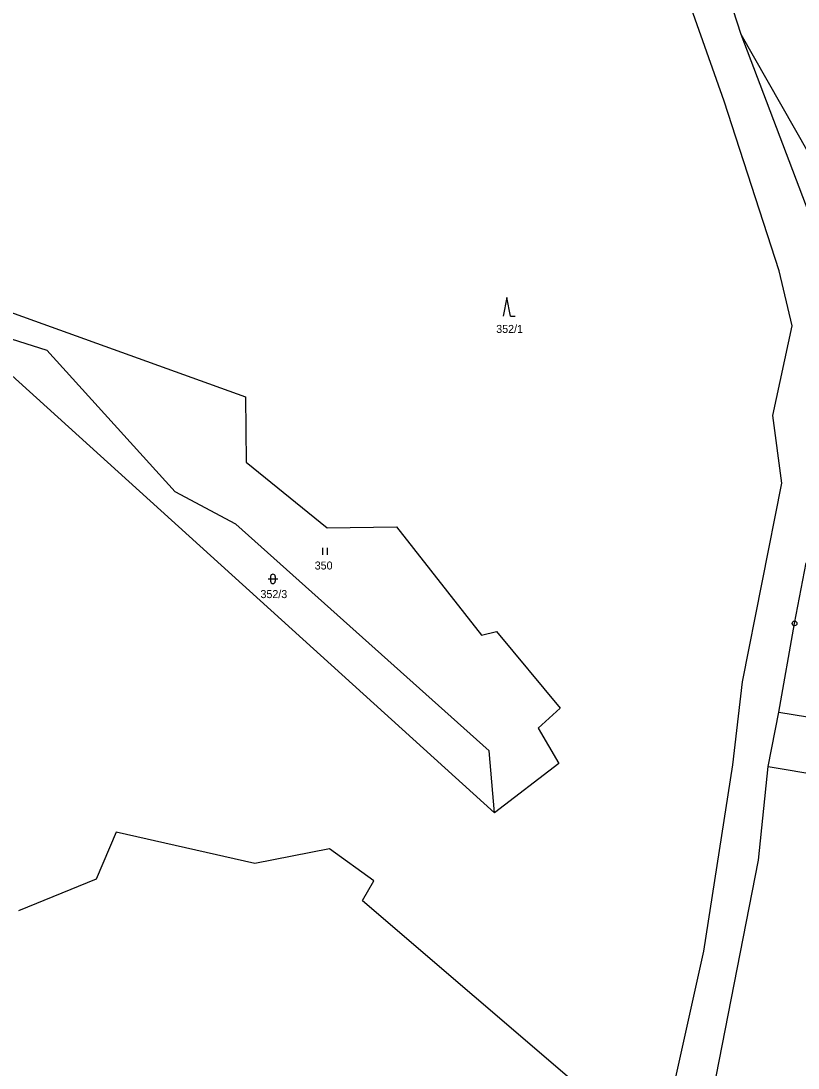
# Model space of a CAD drawing. Extents: x -765428 to -762163, y -1107632 to -1104975.
# Drawn here: x -764056.9 to -763891.8, y -1106861.1 to -1106638.7 of the extents above; entities that cross this region are included whole.
import ezdxf
from ezdxf.enums import TextEntityAlignment as Align

# ---------------------------------------------------------------- set-up
doc = ezdxf.new("R2010")
doc.units = 0
doc.header["$LTSCALE"] = 0.68
for name, color, linetype, lineweight in [('1', 7, 'Continuous', 25), ('3', 7, 'Continuous', 25), ('8', 7, 'Continuous', 25)]:
    doc.layers.add(name, color=color, linetype=linetype, lineweight=lineweight)
doc.layers.add('2', color=7, linetype='Continuous')

msp = doc.modelspace()

# ---------------------------------------------------------------- linework, layer by layer
at = {"layer": '1'}
for p, q in [((-763903.89, -1106641.54), (-763907.81, -1106629.35)), ((-763907.5, -1106655.7), (-763916.81, -1106629.4)), ((-763885.2, -1106690.82), (-763903.89, -1106641.54)), ((-763879.14, -1106685.04), (-763903.89, -1106641.54)), ((-763895.8, -1106691.78), (-763907.5, -1106655.7)), ((-763893.05, -1106703.44), (-763895.8, -1106691.78)), ((-764062.06, -1106699.52), (-764009.24, -1106718.56)), ((-763956.29, -1106806.86), (-764072.04, -1106702.13)), ((-764063.68, -1106704.76), (-764051.43, -1106708.61)), ((-763897.13, -1106722.5), (-763893.05, -1106703.44)), ((-764024.19, -1106738.74), (-764051.43, -1106708.61)), ((-764009.24, -1106718.56), (-764009.1, -1106732.38)), ((-763895.24, -1106736.89), (-763897.13, -1106722.5)), ((-764009.1, -1106732.38), (-763991.88, -1106746.36)), ((-763903.59, -1106779.07), (-763895.24, -1106736.89)), ((-764011.28, -1106745.55), (-764024.19, -1106738.74)), ((-763957.44, -1106793.7), (-764011.28, -1106745.55)), ((-763991.88, -1106746.36), (-763977.12, -1106746.15)), ((-763977.12, -1106746.15), (-763959.06, -1106769.18)), ((-763892.53, -1106766.67), (-763890.05, -1106753.82)), ((-763895.86, -1106785.49), (-763892.53, -1106766.67)), ((-763959.06, -1106769.18), (-763955.87, -1106768.39)), ((-763955.87, -1106768.39), (-763942.34, -1106784.68)), ((-763905.68, -1106796.68), (-763903.59, -1106779.07)), ((-763942.34, -1106784.68), (-763947.03, -1106788.92)), ((-763898.11, -1106797.01), (-763895.86, -1106785.49)), ((-763895.86, -1106785.49), (-763877.07, -1106788.59)), ((-763947.03, -1106788.92), (-763942.66, -1106796.43)), ((-763956.29, -1106806.86), (-763957.44, -1106793.7)), ((-763942.66, -1106796.43), (-763956.29, -1106806.86)), ((-763911.84, -1106836.29), (-763905.68, -1106796.68)), ((-763900.2, -1106816.93), (-763898.11, -1106797.01)), ((-763898.11, -1106797.01), (-763878.91, -1106800.35)), ((-764036.73, -1106810.99), (-764040.99, -1106820.96)), ((-764007.25, -1106817.68), (-764036.73, -1106810.99)), ((-763991.34, -1106814.51), (-764007.25, -1106817.68)), ((-763981.95, -1106821.35), (-763991.34, -1106814.51)), ((-763910.6, -1106870.13), (-763900.2, -1106816.93)), ((-764040.99, -1106820.96), (-764057.46, -1106827.68)), ((-763984.36, -1106825.5), (-763981.95, -1106821.35)), ((-763984.36, -1106825.5), (-763927.16, -1106874.4)), ((-763918.21, -1106864.97), (-763911.84, -1106836.29))]:
    msp.add_line(p, q, dxfattribs=at)
at = {"layer": '3'}
for p, q in [((-763952.93, -1106701.41), (-763951.934, -1106701.41)), ((-763992.801, -1106752.08), (-763992.801, -1106750.58)), ((-763991.8, -1106752.08), (-763991.8, -1106750.58)), ((-764004.381, -1106757.191), (-764002.379, -1106757.191)), ((-764003.881, -1106756.691), (-764003.881, -1106757.692)), ((-764002.879, -1106757.692), (-764002.879, -1106756.691))]:
    msp.add_line(p, q, dxfattribs=at)
msp.add_lwpolyline([(-763952.93, -1106701.41), (-763953.68, -1106697.41), (-763954.43, -1106701.41)], dxfattribs=at)
for centre, start, end in [((-764003.38, -1106756.6909), 0, 180), ((-764003.38, -1106757.6909), 180, 359.98789)]:
    msp.add_arc(centre, 0.5, start, end, dxfattribs=at)
at = {"layer": '8'}
for radius in [0.5, 0.0303]:
    msp.add_circle((-763892.53, -1106766.6699), radius, dxfattribs=at)

# ---------------------------------------------------------------- texts
at = {"layer": '2'}
msp.add_text('352/1', height=1.7, dxfattribs=at).set_placement((-763953.09, -1106704.955), align=Align.CENTER)
for s, p in [('350', (-763994.51, -1106755.205)), ('352/3', (-764006.04, -1106761.275))]:
    msp.add_text(s, height=1.7, dxfattribs=at).set_placement(p)

doc.saveas('drawing.dxf')
